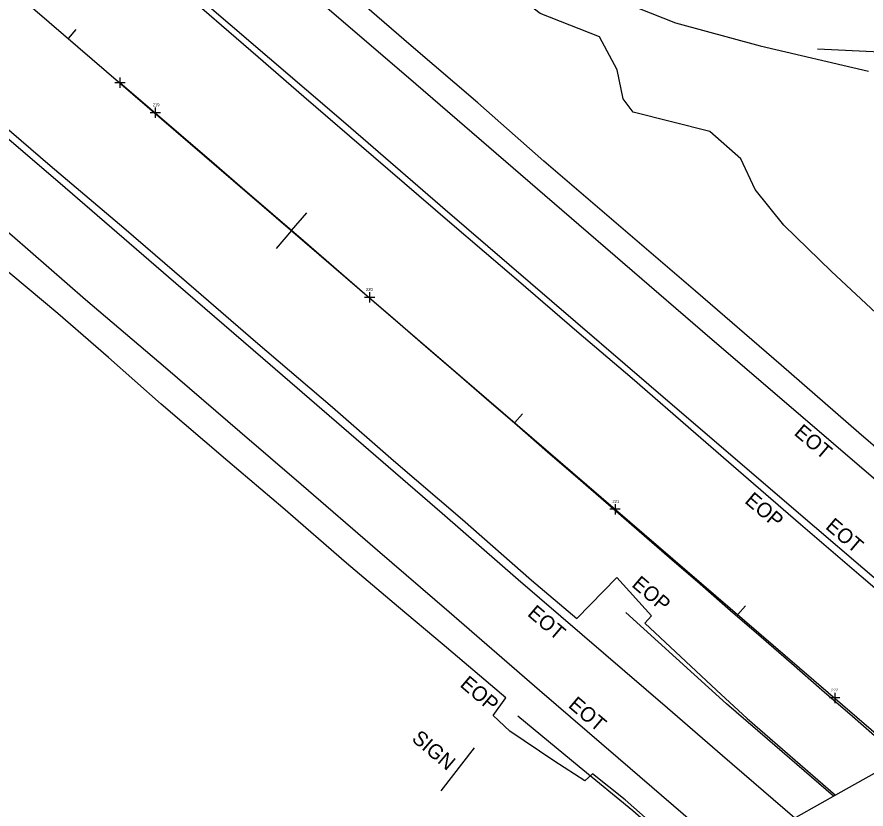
# Model space of a CAD drawing. Extents: x 2076109 to 2080761, y 592812 to 596750.
# Drawn here: x 2076996.8 to 2077285.2, y 595772.6 to 596041.6 of the extents above; entities that cross this region are included whole.
import ezdxf

# ---------------------------------------------------------------- set-up
doc = ezdxf.new("R2010")
doc.units = 0
for name, color, linetype in [('Default', 7, 'Continuous'), ('RD_EX_BldgApp', 7, 'Continuous'), ('RD_EX_BldgApp_txCode', 7, 'Continuous'), ('RD_EX_Bridge', 7, 'Continuous'), ('RD_EX_Fence_ChLk', 7, 'Continuous'), ('RD_EX_GuardRail', 7, 'Continuous'), ('RD_EX_Misc', 7, 'Continuous'), ('RD_EX_Misc_txCode', 7, 'Continuous'), ('RD_EX_Road', 7, 'Continuous'), ('RD_EX_Road_txCode', 7, 'Continuous'), ('RD_EX_VEG', 7, 'Continuous'), ('RD_HC_Cl', 7, 'Continuous'), ('RD_HC_Data_Tic', 7, 'Continuous')]:
    doc.layers.add(name, color=color, linetype=linetype)

msp = doc.modelspace()

# ---------------------------------------------------------------- linework, layer by layer
at = {"layer": 'Default'}
for p, q in [((2077031.74, 596020.95), (2077031.74, 596017.45)), ((2077031.74, 596020.95), (2077031.74, 596017.45)), ((2077033.49, 596019.2), (2077029.99, 596019.2)), ((2077033.49, 596019.2), (2077029.99, 596019.2)), ((2077045.51, 596009.05), (2077042.01, 596009.05)), ((2077045.51, 596009.05), (2077042.01, 596009.05)), ((2077043.76, 596010.8), (2077043.76, 596007.3)), ((2077043.76, 596010.8), (2077043.76, 596007.3)), ((2077116.55, 595948.07), (2077116.55, 595944.57)), ((2077116.55, 595948.07), (2077116.55, 595944.57)), ((2077118.3, 595946.32), (2077114.8, 595946.32)), ((2077118.3, 595946.32), (2077114.8, 595946.32)), ((2077199.97, 595876.1), (2077199.97, 595872.6)), ((2077199.97, 595876.1), (2077199.97, 595872.6)), ((2077201.72, 595874.35), (2077198.22, 595874.35)), ((2077201.72, 595874.35), (2077198.22, 595874.35)), ((2077276.34, 595810.28), (2077272.84, 595810.28)), ((2077276.34, 595810.28), (2077272.84, 595810.28)), ((2077274.59, 595812.03), (2077274.59, 595808.53)), ((2077274.59, 595812.03), (2077274.59, 595808.53))]:
    msp.add_line(p, q, dxfattribs=at)
msp.add_arc((2035586.7, 547847.96), 63546.51, 48.5011873, 49.2923126, dxfattribs=at)
msp.add_arc((2035586.7, 547847.96), 63546.51, 48.5011873, 49.2923126, dxfattribs=at)
at = {"layer": 'RD_EX_BldgApp'}
msp.add_line((2077152.12, 595793.33), (2077140.79, 595778.7), dxfattribs=at)
msp.add_line((2077152.12, 595793.33), (2077140.79, 595778.7), dxfattribs=at)
at = {"layer": 'RD_EX_Bridge'}
msp.add_lwpolyline([(2077182.69, 595725.56), (2077226.26, 595749.95), (2077278.63, 595779.43), (2077318.69, 595801.87), (2077370.98, 595831.15), (2077414.59, 595855.59), (2077438.98, 595834.26), (2077395.4, 595809.74), (2077342.89, 595780.4), (2077302.73, 595757.84), (2077250.38, 595728.31), (2077206.95, 595704.06)], close=True, dxfattribs=at)
msp.add_lwpolyline([(2077182.69, 595725.56), (2077226.26, 595749.95), (2077278.63, 595779.43), (2077318.69, 595801.87), (2077370.98, 595831.15), (2077414.59, 595855.59), (2077438.98, 595834.26), (2077395.4, 595809.74), (2077342.89, 595780.4), (2077302.73, 595757.84), (2077250.38, 595728.31), (2077206.95, 595704.06)], close=True, dxfattribs=at)
at = {"layer": 'RD_EX_Fence_ChLk'}
msp.add_lwpolyline([(2077268.73, 596030.73), (2077313.72, 596028.64), (2077376.27, 596039.18), (2077416.08, 596025.9)], dxfattribs=at)
msp.add_lwpolyline([(2077268.73, 596030.73), (2077313.72, 596028.64), (2077376.27, 596039.18), (2077416.08, 596025.9)], dxfattribs=at)
at = {"layer": 'RD_EX_GuardRail'}
for points in [[(2077274.19, 595776.93), (2077251.71, 595796.28), (2077237.81, 595808.31), (2077203.64, 595839.29)], [(2077274.19, 595776.93), (2077251.71, 595796.28), (2077237.81, 595808.31), (2077203.64, 595839.29)], [(2077166.87, 595804.2), (2077187.8, 595787), (2077205.99, 595772.02), (2077221.94, 595758.11), (2077229.35, 595751.69)], [(2077166.87, 595804.2), (2077187.8, 595787), (2077205.99, 595772.02), (2077221.94, 595758.11), (2077229.35, 595751.69)]]:
    msp.add_lwpolyline(points, dxfattribs=at)
at = {"layer": 'RD_EX_Misc'}
for points in [[(2076810.47, 596295.64), (2076861.8, 596251.39), (2076900.57, 596218.06), (2076940.76, 596183.48), (2076983.39, 596147), (2077038.07, 596099.91), (2077086.97, 596057.78), (2077132.28, 596018.8), (2077181.85, 595976.05), (2077229.69, 595934.91), (2077274.19, 595896.66), (2077329.2, 595849.52), (2077358.6, 595824.22)], [(2076810.47, 596295.64), (2076861.8, 596251.39), (2076900.57, 596218.06), (2076940.76, 596183.48), (2076983.39, 596147), (2077038.07, 596099.91), (2077086.97, 596057.78), (2077132.28, 596018.8), (2077181.85, 595976.05), (2077229.69, 595934.91), (2077274.19, 595896.66), (2077329.2, 595849.52), (2077358.6, 595824.22)], [(2077334.93, 595810.96), (2077327.55, 595817.3), (2077300.53, 595840.37), (2077267.76, 595868.37), (2077240.07, 595892.05), (2077211.41, 595916.6), (2077178.43, 595944.97), (2077142.26, 595976.09), (2077108.47, 596005.28), (2077069.23, 596038.87), (2077039.16, 596064.68), (2077006.35, 596092.75), (2076967.21, 596126.45), (2076935.59, 596153.65), (2076905.14, 596179.73), (2076872.01, 596208.18), (2076841.3, 596234.65), (2076810.18, 596261.57), (2076792.25, 596277.09)], [(2077334.93, 595810.96), (2077327.55, 595817.3), (2077300.53, 595840.37), (2077267.76, 595868.37), (2077240.07, 595892.05), (2077211.41, 595916.6), (2077178.43, 595944.97), (2077142.26, 595976.09), (2077108.47, 596005.28), (2077069.23, 596038.87), (2077039.16, 596064.68), (2077006.35, 596092.75), (2076967.21, 596126.45), (2076935.59, 596153.65), (2076905.14, 596179.73), (2076872.01, 596208.18), (2076841.3, 596234.65), (2076810.18, 596261.57), (2076792.25, 596277.09)], [(2076740.94, 596217.33), (2076779.88, 596183.77), (2076827.32, 596143.01), (2076861.06, 596114.09), (2076898.34, 596082.26), (2076930.17, 596054.83), (2076977.99, 596013.66), (2077013.1, 595983.67), (2077050.75, 595951.15), (2077080.28, 595925.68), (2077141.22, 595873.03), (2077167.07, 595850.5), (2077217.75, 595806.94), (2077236.47, 595790.71), (2077261.03, 595769.53)], [(2076740.94, 596217.33), (2076779.88, 596183.77), (2076827.32, 596143.01), (2076861.06, 596114.09), (2076898.34, 596082.26), (2076930.17, 596054.83), (2076977.99, 596013.66), (2077013.1, 595983.67), (2077050.75, 595951.15), (2077080.28, 595925.68), (2077141.22, 595873.03), (2077167.07, 595850.5), (2077217.75, 595806.94), (2077236.47, 595790.71), (2077261.03, 595769.53)], [(2077238.94, 595757.09), (2077227.22, 595767.31), (2077200.97, 595789.86), (2077174.3, 595812.85), (2077143.56, 595839.45), (2077119.23, 595860.41), (2077093.27, 595882.76), (2077072.46, 595900.64), (2077047.17, 595922.37), (2077020.07, 595945.55), (2076995.16, 595967.19), (2076973.2, 595985.95), (2076950.94, 596005.11), (2076925.46, 596027.1), (2076903.87, 596045.6), (2076877.62, 596068.1), (2076855.08, 596087.36), (2076831.5, 596107.64), (2076806.02, 596129.35), (2076775.58, 596155.55), (2076743.51, 596183.09), (2076721.01, 596202.46)], [(2077238.94, 595757.09), (2077227.22, 595767.31), (2077200.97, 595789.86), (2077174.3, 595812.85), (2077143.56, 595839.45), (2077119.23, 595860.41), (2077093.27, 595882.76), (2077072.46, 595900.64), (2077047.17, 595922.37), (2077020.07, 595945.55), (2076995.16, 595967.19), (2076973.2, 595985.95), (2076950.94, 596005.11), (2076925.46, 596027.1), (2076903.87, 596045.6), (2076877.62, 596068.1), (2076855.08, 596087.36), (2076831.5, 596107.64), (2076806.02, 596129.35), (2076775.58, 596155.55), (2076743.51, 596183.09), (2076721.01, 596202.46)]]:
    msp.add_lwpolyline(points, dxfattribs=at)
at = {"layer": 'RD_EX_Road'}
for points in [[(2077309.59, 595877.22), (2077282.74, 595900.37), (2077256.36, 595923.26), (2077227.25, 595948.47), (2077198.79, 595972.87), (2077175.8, 595992.64), (2077153.37, 596012.36), (2077130.64, 596031.73), (2077105.62, 596053.51), (2077080.49, 596075.06), (2077051.54, 596099.91), (2077024.4, 596123.26), (2077002.19, 596142.32), (2076978.91, 596162.67), (2076952.21, 596185.24), (2076929.19, 596204.76), (2076902.69, 596227.39), (2076879.24, 596247.55), (2076859.1, 596264.86), (2076833.46, 596286.99), (2076816.41, 596301.99)], [(2077309.59, 595877.22), (2077282.74, 595900.37), (2077256.36, 595923.26), (2077227.25, 595948.47), (2077198.79, 595972.87), (2077175.8, 595992.64), (2077153.37, 596012.36), (2077130.64, 596031.73), (2077105.62, 596053.51), (2077080.49, 596075.06), (2077051.54, 596099.91), (2077024.4, 596123.26), (2077002.19, 596142.32), (2076978.91, 596162.67), (2076952.21, 596185.24), (2076929.19, 596204.76), (2076902.69, 596227.39), (2076879.24, 596247.55), (2076859.1, 596264.86), (2076833.46, 596286.99), (2076816.41, 596301.99)], [(2076790.96, 596275.94), (2076814.77, 596255.12), (2076842.21, 596231.47), (2076870.29, 596207.22), (2076894.79, 596186.02), (2076920.29, 596164.11), (2076947.36, 596141.05), (2076969.17, 596122), (2076994.72, 596100.04), (2077020.61, 596077.66), (2077049.58, 596053.31), (2077078.66, 596028.07), (2077094.19, 596014.5), (2077117.9, 595994.16), (2077143.78, 595971.83), (2077167.12, 595951.98), (2077186.93, 595934.87), (2077205.77, 595918.84), (2077227.43, 595900.11), (2077245.34, 595884.56), (2077262.98, 595869.29), (2077283.52, 595851.63), (2077302.45, 595835.44)], [(2076790.96, 596275.94), (2076814.77, 596255.12), (2076842.21, 596231.47), (2076870.29, 596207.22), (2076894.79, 596186.02), (2076920.29, 596164.11), (2076947.36, 596141.05), (2076969.17, 596122), (2076994.72, 596100.04), (2077020.61, 596077.66), (2077049.58, 596053.31), (2077078.66, 596028.07), (2077094.19, 596014.5), (2077117.9, 595994.16), (2077143.78, 595971.83), (2077167.12, 595951.98), (2077186.93, 595934.87), (2077205.77, 595918.84), (2077227.43, 595900.11), (2077245.34, 595884.56), (2077262.98, 595869.29), (2077283.52, 595851.63), (2077302.45, 595835.44)], [(2076981.65, 596013.78), (2077008.04, 595991.17), (2077033.1, 595969.99), (2077057.6, 595948.79), (2077077.83, 595931.36), (2077103.94, 595909.02), (2077124.67, 595890.93), (2077148.13, 595870.9), (2077171.61, 595850.29), (2077187.02, 595837.23), (2077200.52, 595851.16), (2077212.37, 595838.14), (2077210.06, 595835.63), (2077234.37, 595812.97), (2077244.85, 595803.28), (2077274.88, 595777.32)], [(2076981.65, 596013.78), (2077008.04, 595991.17), (2077033.1, 595969.99), (2077057.6, 595948.79), (2077077.83, 595931.36), (2077103.94, 595909.02), (2077124.67, 595890.93), (2077148.13, 595870.9), (2077171.61, 595850.29), (2077187.02, 595837.23), (2077200.52, 595851.16), (2077212.37, 595838.14), (2077210.06, 595835.63), (2077234.37, 595812.97), (2077244.85, 595803.28), (2077274.88, 595777.32)], [(2077225.85, 595755.89), (2077203.36, 595775.66), (2077192.29, 595784.56), (2077189.7, 595782.1), (2077179.2, 595788.96), (2077164.21, 595798.98), (2077158.52, 595804.28), (2077162.84, 595810.34), (2077141.24, 595828.7), (2077126.35, 595841.08), (2077108.74, 595856.11), (2077087.03, 595874.84), (2077068.37, 595890.75), (2077045.75, 595910.03), (2077027.89, 595925.91), (2077010.62, 595940.91), (2076989.65, 595958.28)], [(2077225.85, 595755.89), (2077203.36, 595775.66), (2077192.29, 595784.56), (2077189.7, 595782.1), (2077179.2, 595788.96), (2077164.21, 595798.98), (2077158.52, 595804.28), (2077162.84, 595810.34), (2077141.24, 595828.7), (2077126.35, 595841.08), (2077108.74, 595856.11), (2077087.03, 595874.84), (2077068.37, 595890.75), (2077045.75, 595910.03), (2077027.89, 595925.91), (2077010.62, 595940.91), (2076989.65, 595958.28)]]:
    msp.add_lwpolyline(points, dxfattribs=at)
at = {"layer": 'RD_EX_VEG'}
msp.add_lwpolyline([(2077296.95, 595933.28), (2077273.45, 595955.1), (2077257.32, 595970.85), (2077247.56, 595983.02), (2077242.74, 595993.39), (2077232.12, 596002.61), (2077206.16, 596009.18), (2077202.7, 596013.78), (2077200.71, 596023.59), (2077194.72, 596034.77), (2077174.54, 596042.71), (2077169.64, 596046.5), (2077167.87, 596048.75), (2077169.25, 596052.55), (2077171.15, 596055), (2077178.1, 596055.36), (2077190.37, 596051.57), (2077220.55, 596039.56), (2077249.3, 596031.71), (2077286.09, 596023.13)], dxfattribs=at)
msp.add_lwpolyline([(2077296.95, 595933.28), (2077273.45, 595955.1), (2077257.32, 595970.85), (2077247.56, 595983.02), (2077242.74, 595993.39), (2077232.12, 596002.61), (2077206.16, 596009.18), (2077202.7, 596013.78), (2077200.71, 596023.59), (2077194.72, 596034.77), (2077174.54, 596042.71), (2077169.64, 596046.5), (2077167.87, 596048.75), (2077169.25, 596052.55), (2077171.15, 596055), (2077178.1, 596055.36), (2077190.37, 596051.57), (2077220.55, 596039.56), (2077249.3, 596031.71), (2077286.09, 596023.13)], dxfattribs=at)
at = {"layer": 'RD_HC_Cl'}
msp.add_line((2076186.59, 596746.26), (2077404.89, 595698.18), dxfattribs=at)
at = {"layer": 'RD_HC_Data_Tic'}
for p, q in [((2077014.26, 596034.23), (2077016.87, 596037.27)), ((2077014.26, 596034.23), (2077016.87, 596037.27)), ((2077090.07, 595969.02), (2077095.29, 595975.08)), ((2077090.07, 595969.02), (2077095.29, 595975.08)), ((2077090.07, 595969.02), (2077084.85, 595962.95)), ((2077090.07, 595969.02), (2077084.85, 595962.95)), ((2077165.88, 595903.8), (2077168.49, 595906.83)), ((2077165.88, 595903.8), (2077168.49, 595906.83)), ((2077241.69, 595838.59), (2077244.3, 595841.62)), ((2077241.69, 595838.59), (2077244.3, 595841.62))]:
    msp.add_line(p, q, dxfattribs=at)

# ---------------------------------------------------------------- texts
at = {"layer": 'Default'}
for s, p in [('219', (2077042.87, 596011.25)), ('219', (2077042.87, 596011.25)), ('220', (2077115.33, 595948.52)), ('220', (2077115.33, 595948.52)), ('221', (2077199.08, 595876.55)), ('221', (2077199.08, 595876.55)), ('222', (2077273.41, 595812.48)), ('222', (2077273.41, 595812.48))]:
    msp.add_text(s, height=1, dxfattribs=at).set_placement(p)
at = {"layer": 'RD_EX_BldgApp_txCode'}
msp.add_text('SIGN', height=5, rotation=319.6274, dxfattribs=at).set_placement((2077130.56, 595795.96))
msp.add_text('SIGN', height=5, rotation=319.6274, dxfattribs=at).set_placement((2077130.56, 595795.96))
at = {"layer": 'RD_EX_Misc_txCode'}
for p in [(2077260.49, 595899.88), (2077260.49, 595899.88), (2077271.14, 595868.04), (2077271.14, 595868.04), (2077169.89, 595838.46), (2077169.89, 595838.46), (2077183.77, 595807.38), (2077183.77, 595807.38)]:
    msp.add_text('EOT', height=5, rotation=319.6274, dxfattribs=at).set_placement(p)
at = {"layer": 'RD_EX_Road_txCode'}
for p in [(2077243.71, 595876.79), (2077243.71, 595876.79), (2077205.33, 595848.36), (2077205.33, 595848.36), (2077146.96, 595814.42), (2077146.96, 595814.42)]:
    msp.add_text('EOP', height=5, rotation=319.6274, dxfattribs=at).set_placement(p)

doc.saveas('drawing.dxf')
